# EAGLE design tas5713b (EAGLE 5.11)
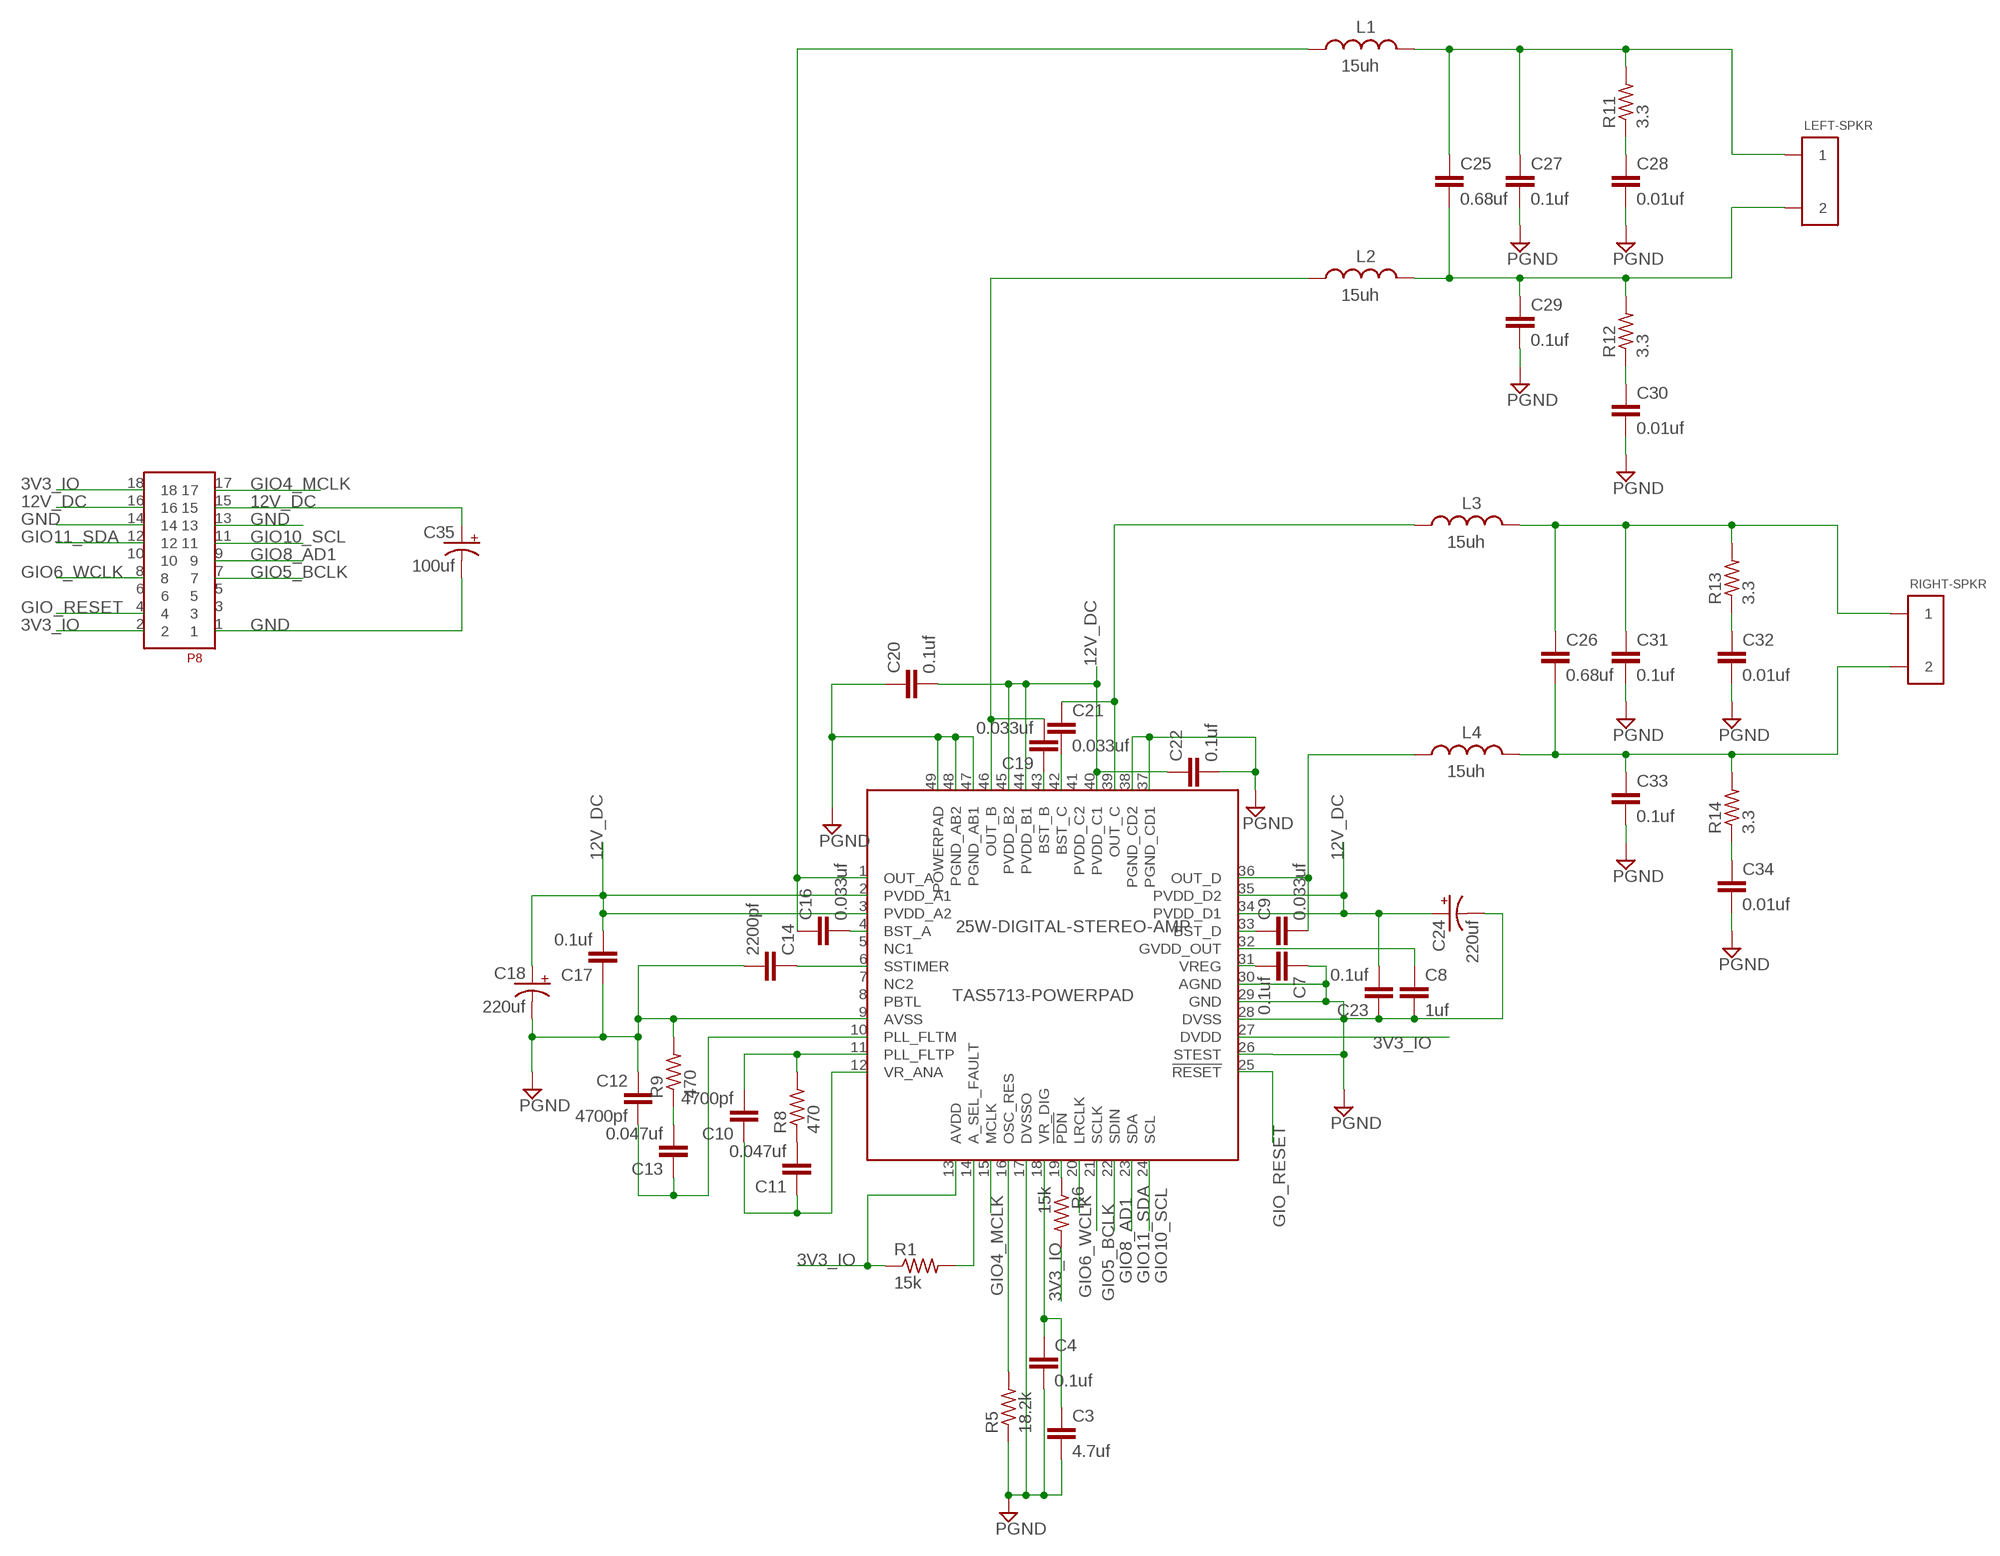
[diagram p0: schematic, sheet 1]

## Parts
25W-DIGITAL-STEREO-AMP  TAS5713-POWERPAD  [SCHMARTBOARD-VQFN48-POWERPAD]
C3  4.7uf  C-EUC1206  [C1206]
C4  0.1uf  C-EUC1206  [C1206]
C7  0.1uf  C-EUC1206  [C1206]
C8  1uf  C-EUC1206  [C1206]
C9  0.033uf  C-EUC1206  [C1206]
C10  4700pf  C-EUC1206  [C1206]
C11  0.047uf  C-EUC1206  [C1206]
C12  4700pf  C-EUC1206  [C1206]
C13  0.047uf  C-EUC1206  [C1206]
C14  2200pf  C-EUC1206  [C1206]
C16  0.033uf  C-EUC1206  [C1206]
C17  0.1uf  C-EUC1206  [C1206]
C18  220uf  CPOL-US175TMP-0808  [175TMP-0808]
C19  0.033uf  C-EUC1206  [C1206]
C20  0.1uf  C-EUC1206  [C1206]
C21  0.033uf  C-EUC1206  [C1206]
C22  0.1uf  C-EUC1206  [C1206]
C23  0.1uf  C-EUC1206  [C1206]
C24  220uf  CPOL-US175TMP-0808  [175TMP-0808]
C25  0.68uf  C-EUC1206  [C1206]
C26  0.68uf  C-EUC1206  [C1206]
C27  0.1uf  C-EUC1206  [C1206]
C28  0.01uf  C-EUC1206  [C1206]
C29  0.1uf  C-EUC1206  [C1206]
C30  0.01uf  C-EUC1206  [C1206]
C31  0.1uf  C-EUC1206  [C1206]
C32  0.01uf  C-EUC1206  [C1206]
C33  0.1uf  C-EUC1206  [C1206]
C34  0.01uf  C-EUC1206  [C1206]
C35  100uf  CPOL-US175TMP-0808  [175TMP-0808]
L1  15uh  INDUCTOR-ABRACON-1306S  [INDUCTOR-ABRACON-1306S]
L2  15uh  INDUCTOR-ABRACON-1306S  [INDUCTOR-ABRACON-1306S]
L3  15uh  INDUCTOR-ABRACON-1306S  [INDUCTOR-ABRACON-1306S]
L4  15uh  INDUCTOR-ABRACON-1306S  [INDUCTOR-ABRACON-1306S]
LEFT-SPKR  SCREW-CLAMP-2909  [SCREW-CLAMP-909]
P8  HEADER-2X9  [HEADER-2X9]
R1  15k  R-US_R1206  [R1206]
R5  18.2k  R-US_R1206  [R1206]
R6  15k  R-US_R1206  [R1206]
R8  470  R-US_R1206  [R1206]
R9  470  R-US_R1206  [R1206]
R11  3.3  R-US_R1206  [R1206]
R12  3.3  R-US_R1206  [R1206]
R13  3.3  R-US_R1206  [R1206]
R14  3.3  R-US_R1206  [R1206]
RIGHT-SPKR  SCREW-CLAMP-2909  [SCREW-CLAMP-909]

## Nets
3V3_IO: 25W-DIGITAL-STEREO-AMP.13(AVDD) 25W-DIGITAL-STEREO-AMP.27(DVDD) P8.2 P8.18 R1.1 R6.2
12V_DC: 25W-DIGITAL-STEREO-AMP.2(PVDD_A1) 25W-DIGITAL-STEREO-AMP.3(PVDD_A2) 25W-DIGITAL-STEREO-AMP.34(PVDD_D1) 25W-DIGITAL-STEREO-AMP.35(PVDD_D2) 25W-DIGITAL-STEREO-AMP.40(PVDD_C1) 25W-DIGITAL-STEREO-AMP.44(PVDD_B1) 25W-DIGITAL-STEREO-AMP.45(PVDD_B2) C17.2 C18.+ C20.2 C22.1 C23.2 C24.+ C35.+ P8.15 P8.16
GIO4_MCLK: 25W-DIGITAL-STEREO-AMP.15(MCLK) P8.17
GIO5_BCLK: 25W-DIGITAL-STEREO-AMP.21(SCLK) P8.7
GIO6_WCLK: 25W-DIGITAL-STEREO-AMP.20(LRCLK) P8.8
GIO8_AD1: 25W-DIGITAL-STEREO-AMP.22(SDIN) P8.9
GIO10_SCL: 25W-DIGITAL-STEREO-AMP.24(SCL) P8.11
GIO11_SDA: 25W-DIGITAL-STEREO-AMP.23(SDA) P8.12
GIO_RESET: 25W-DIGITAL-STEREO-AMP.25(!RESET) P8.4
GND: 25W-DIGITAL-STEREO-AMP.9(AVSS) 25W-DIGITAL-STEREO-AMP.17(DVSSO) 25W-DIGITAL-STEREO-AMP.26(STEST) 25W-DIGITAL-STEREO-AMP.28(DVSS) 25W-DIGITAL-STEREO-AMP.29(GND) 25W-DIGITAL-STEREO-AMP.30(AGND) 25W-DIGITAL-STEREO-AMP.37(PGND_CD1) 25W-DIGITAL-STEREO-AMP.38(PGND_CD2) 25W-DIGITAL-STEREO-AMP.47(PGND_AB1) 25W-DIGITAL-STEREO-AMP.48(PGND_AB2) 25W-DIGITAL-STEREO-AMP.49(POWERPAD) C3.2 C4.2 C7.1 C8.2 C12.1 C14.2 C17.1 C18.- C20.1 C22.2 C23.1 C24.- C27.2 C28.2 C29.2 C30.2 C31.2 C32.2 C33.2 C34.2 C35.- P8.1 P8.13 P8.14 R5.1 R9.2 ; supply symbol labelled PGND
N$1: 25W-DIGITAL-STEREO-AMP.4(BST_A) C16.2
N$2: 25W-DIGITAL-STEREO-AMP.1(OUT_A) C16.1 L1.1
N$3: 25W-DIGITAL-STEREO-AMP.43(BST_B) C19.1
N$4: 25W-DIGITAL-STEREO-AMP.46(OUT_B) C19.2 L2.1
N$5: 25W-DIGITAL-STEREO-AMP.42(BST_C) C21.2
N$6: 25W-DIGITAL-STEREO-AMP.14(A_SEL_FAULT) R1.2
N$7: 25W-DIGITAL-STEREO-AMP.33(BST_D) C9.1
N$8: 25W-DIGITAL-STEREO-AMP.36(OUT_D) C9.2 L4.1
N$9: 25W-DIGITAL-STEREO-AMP.31(VREG) C7.2
N$10: 25W-DIGITAL-STEREO-AMP.32(GVDD_OUT) C8.1
N$11: 25W-DIGITAL-STEREO-AMP.6(SSTIMER) C14.1
N$12: C28.1 R11.1
N$13: C25.2 C29.1 L2.2 LEFT-SPKR.2 R12.2
N$14: C30.1 R12.1
N$15: 25W-DIGITAL-STEREO-AMP.39(OUT_C) C21.1 L3.1
N$16: 25W-DIGITAL-STEREO-AMP.18(VR_DIG) C3.1 C4.1
N$17: 25W-DIGITAL-STEREO-AMP.16(OSC_RES) R5.2
N$18: C26.1 C31.1 L3.2 R13.2 RIGHT-SPKR.1
N$19: C25.1 C27.1 L1.2 LEFT-SPKR.1 R11.2
N$20: C32.1 R13.1
N$21: C26.2 C33.1 L4.2 R14.2 RIGHT-SPKR.2
N$22: C34.1 R14.1
N$23: 25W-DIGITAL-STEREO-AMP.19(!PDN) R6.1
N$24: 25W-DIGITAL-STEREO-AMP.10(PLL_FLTM) C12.2 C13.1
N$25: 25W-DIGITAL-STEREO-AMP.11(PLL_FLTP) C10.2 R8.2
N$26: 25W-DIGITAL-STEREO-AMP.12(VR_ANA) C10.1 C11.1
N$27: C11.2 R8.1
N$28: C13.2 R9.1
Unconnected: 25W-DIGITAL-STEREO-AMP.5(NC1) 25W-DIGITAL-STEREO-AMP.7(NC2) 25W-DIGITAL-STEREO-AMP.8(PBTL) 25W-DIGITAL-STEREO-AMP.41(PVDD_C2) P8.3 P8.5 P8.6 P8.10

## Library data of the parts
25W-DIGITAL-STEREO-AMP = trl:TAS5713-POWERPAD
C3 C4 C7-C14 C16 C17 C19-C23 C25-C34 = rcl:C-EU: CAPACITOR, European symbol
C18 C24 C35 = resistor:CPOL-US: POLARIZED CAPACITOR, American symbol
L1-L4 = trl:INDUCTOR-ABRACON-1306S
LEFT-SPKR RIGHT-SPKR = trl:SCREW-CLAMP-2
P8 = trl:HEADER-2X9
R1 R5 R6 R8 R9 R11-R14 = resistor:R-US_: RESISTOR, American symbol

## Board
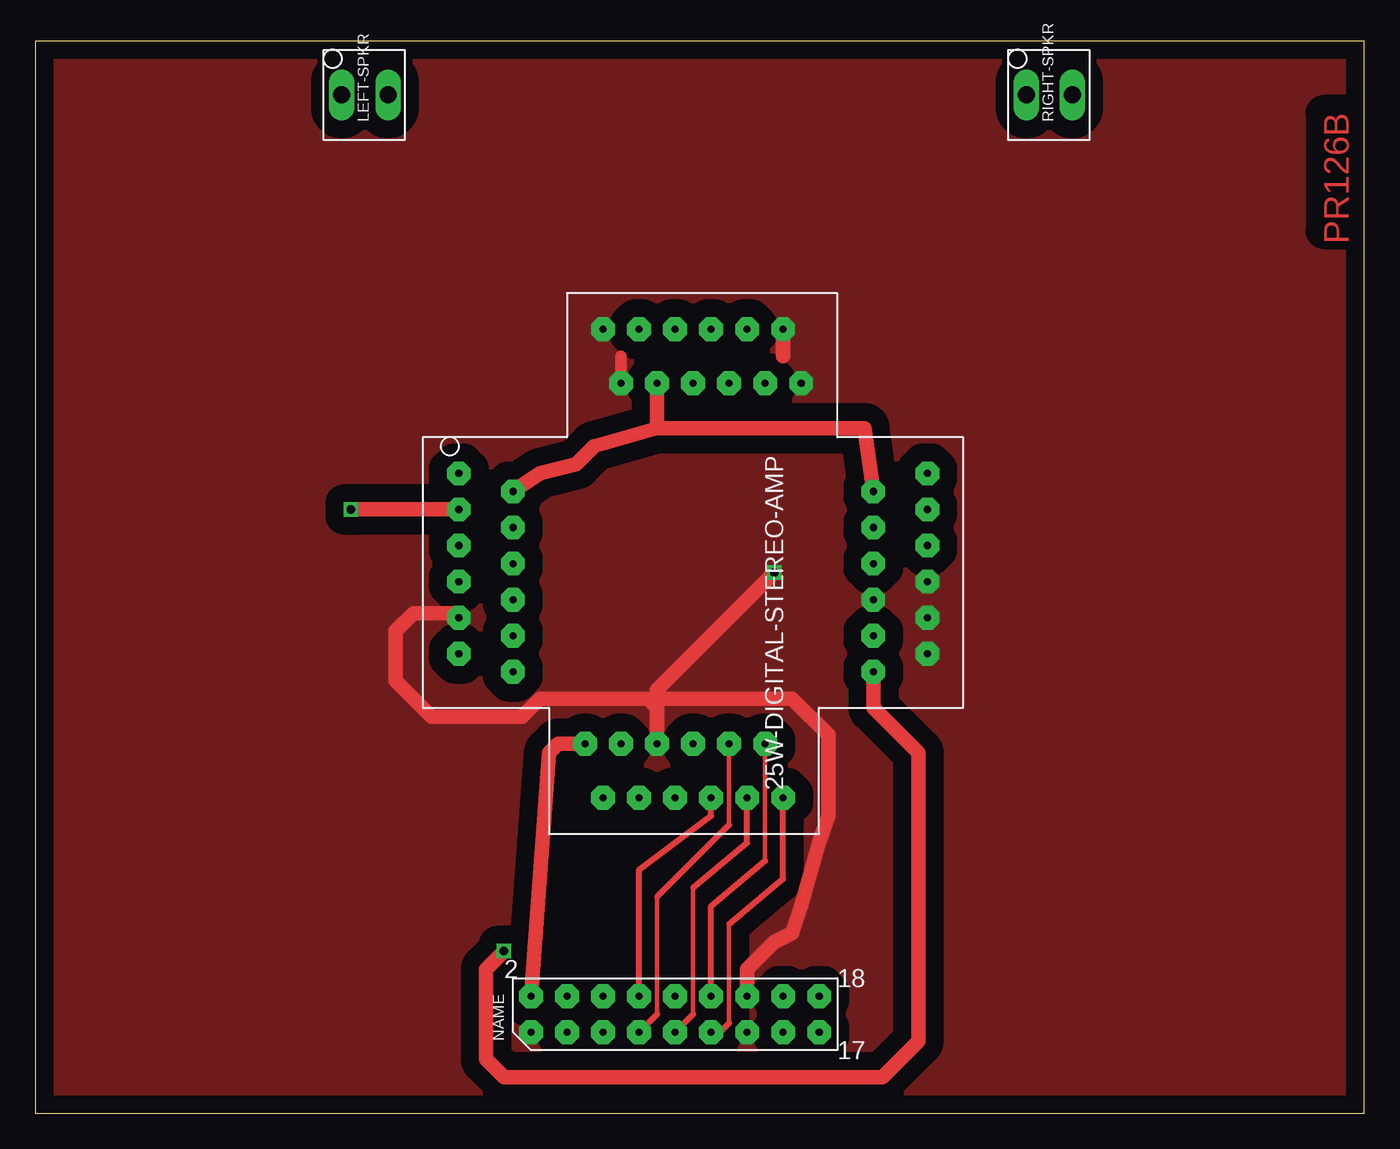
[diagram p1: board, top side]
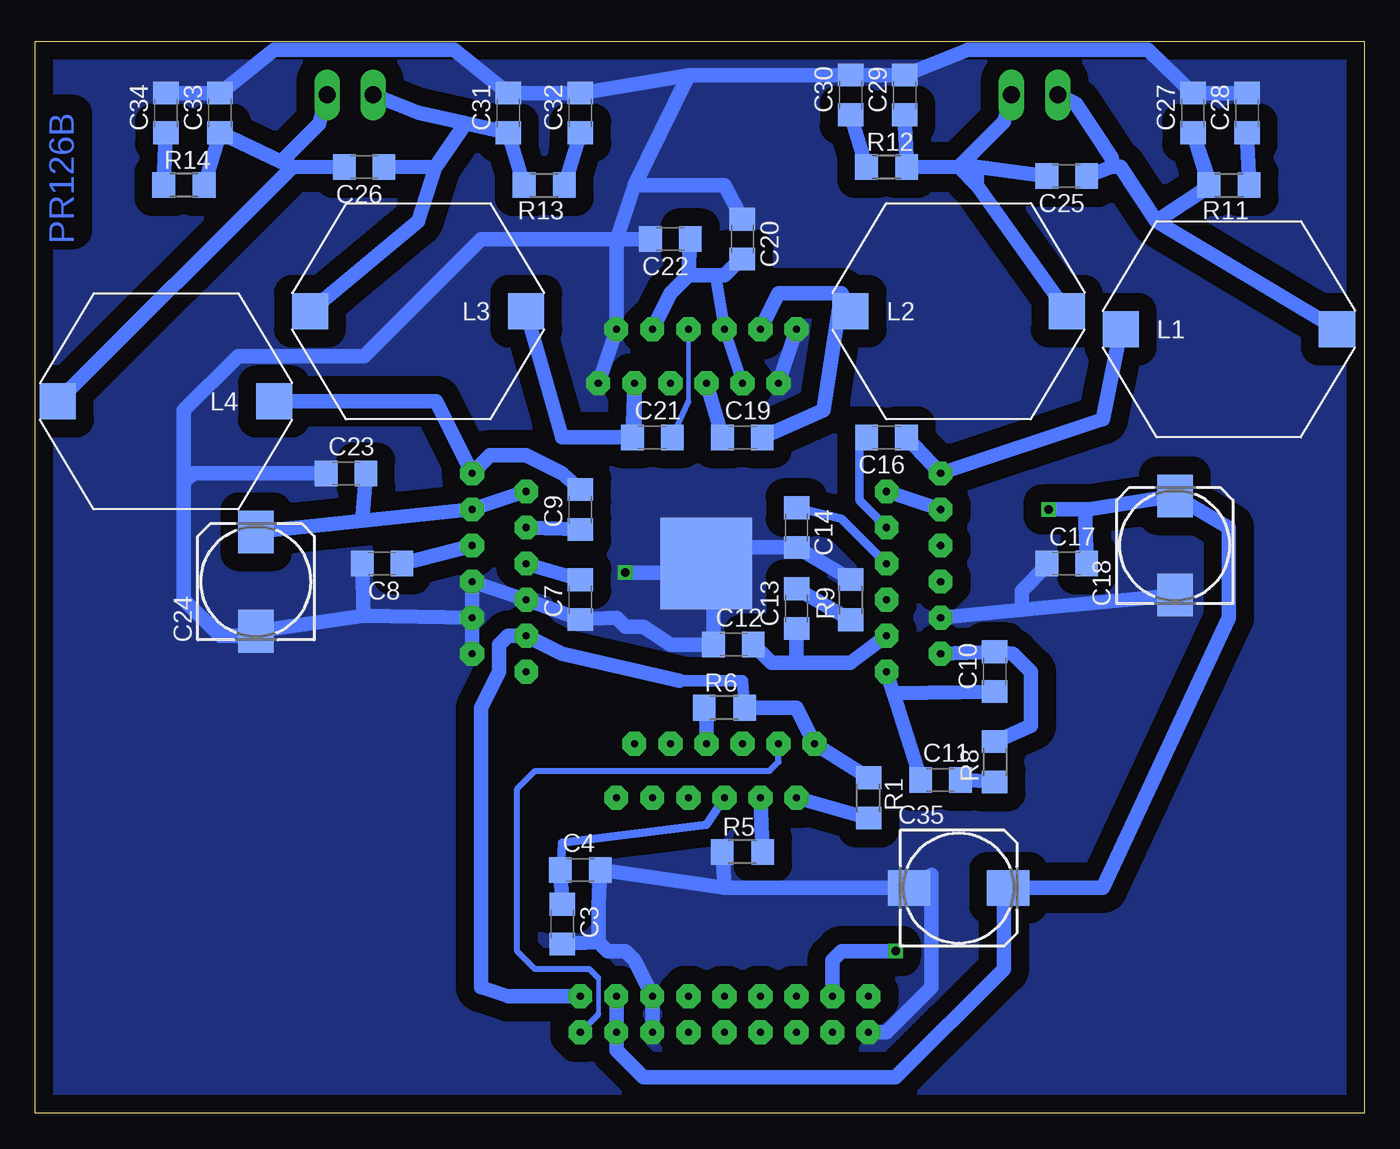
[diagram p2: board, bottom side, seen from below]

Size 93.65 x 75.56 mm. Coordinates in mm from the lower left corner, seen from the top.
Outline: 0,0 93.65,0 93.65,75.56 0,75.56 0,0
Copper layers (1*16): Top 0.035mm / dielectric 1.5mm / Bottom 0.035mm
Design rules "default": minimum track width 10mil, minimum drill 24mil, track to track 8mil, track to pad 8mil, pad to pad 8mil, via to via 8mil, smd to smd 8mil, copper to edge 40mil, drill to drill 8mil, minimum pad ring 10mil, minimum via ring 8mil, stop-mask expansion 4mil, vias tented up to drill 0mil, thermal gap 10mil

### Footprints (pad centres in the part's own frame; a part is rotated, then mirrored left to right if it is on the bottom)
SCHMARTBOARD-VQFN48-POWERPAD = drill 0.5 pad 1.676 octagon: 1 -6.35,-16.51; 2 -5.08,-12.7; 3 -3.81,-16.51; 4 -2.54,-12.7; 5 -1.27,-16.51; 6 0,-12.7; 7 1.27,-16.51; 8 2.54,-12.7; 9 3.81,-16.51; 10 5.08,-12.7; 11 6.35,-16.51; 12 7.62,-12.7; 13 12.7,-7.62; 14 16.51,-6.35; 15 12.7,-5.08; 16 16.51,-3.81; 17 12.7,-2.54; 18 16.51,-1.27; 19 12.7,0; 20 16.51,1.27; 21 12.7,2.54; 22 16.51,3.81; 23 12.7,5.08; 24 16.51,6.35; 25 7.62,12.7; 26 6.35,16.51; 27 5.08,12.7; 28 3.81,16.51; 29 2.54,12.7; 30 1.27,16.51; 31 0,12.7; 32 -1.27,16.51; 33 -2.54,12.7; 34 -3.81,16.51; 35 -5.08,12.7; 36 -6.35,16.51; 37 -12.7,7.62; 38 -16.51,6.35; 39 -12.7,5.08; 40 -16.51,3.81; 41 -12.7,2.54; 42 -16.51,1.27; 43 -12.7,0; 44 -16.51,-1.27; 45 -12.7,-2.54; 46 -16.51,-3.81; 47 -12.7,-5.08; 48 -16.51,-6.35 | smd 6.452 x 6.452 bottom: 49 0,0
C1206 = smd 1.6 x 1.8: 1 -1.4,0; 2 1.4,0
175TMP-0808 = smd 3 x 2.5: + 3.5,0; - -3.5,0
INDUCTOR-ABRACON-1306S = smd 2.54 x 2.54: 1 0,0; 2 15.24,0
SCREW-CLAMP-909 = drill 1.2 long: 1 0,0; 2 3.251,0
HEADER-2X9 = drill 0.5 pad 1.676 octagon: 1 -11.43,-1.27; 2 -11.43,1.27; 3 -8.89,-1.27; 4 -8.89,1.27; 5 -6.35,-1.27; 6 -6.35,1.27; 7 -3.81,-1.27; 8 -3.81,1.27; 9 -1.27,-1.27; 10 -1.27,1.27; 11 1.27,-1.27; 12 1.27,1.27; 13 3.81,-1.27; 14 3.81,1.27; 15 6.35,-1.27; 16 6.35,1.27; 17 8.89,-1.27; 18 8.89,1.27
R1206 = smd 1.6 x 1.803: 1 -1.422,0; 2 1.422,0

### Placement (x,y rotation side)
25W-DIGITAL-STEREO-AMP  46.35,38.73 270 top
C3  56.52,13.34 270 bottom
C4  55.24,17.14 0 bottom
C7  55.24,36.2 90 bottom
C8  69.22,38.73 180 bottom
C9  55.24,42.55 90 bottom
C10  26.04,31.11 90 bottom
C11  29.84,23.5 0 bottom
C12  44.45,33.02 0 bottom
C13  40.01,35.56 90 bottom
C14  40.01,41.27 270 bottom
C16  33.66,47.62 180 bottom
C17  20.95,38.73 0 bottom
C18  13.34,40.01 90 bottom
C19  43.81,47.62 0 bottom
C20  43.81,61.59 270 bottom
C21  50.16,47.62 0 bottom
C22  48.9,61.59 180 bottom
C23  71.75,45.09 0 bottom
C24  78.11,37.47 90 bottom
C25  20.95,66.04 180 bottom
C26  70.48,66.67 180 bottom
C27  12.06,70.48 90 bottom
C28  8.26,70.48 90 bottom
C29  32.38,71.75 90 bottom
C30  36.2,71.75 90 bottom
C31  60.33,70.48 90 bottom
C32  55.24,70.48 90 bottom
C33  80.64,70.48 90 bottom
C34  84.45,70.48 90 bottom
C35  28.57,15.88 0 bottom
L1  17.14,55.24 0 bottom
L2  36.2,56.52 0 bottom
L3  59.05,56.52 180 bottom
L4  76.83,50.16 180 bottom
LEFT-SPKR  21.59,71.75 0 top
P8  46.35,6.99 0 top
R1  34.92,22.23 270 bottom
R5  43.81,18.41 0 bottom
R6  45.09,28.57 0 bottom
R8  26.04,24.77 90 bottom
R9  36.2,36.2 90 bottom
R11  9.53,65.41 180 bottom
R12  33.66,66.67 0 bottom
R13  57.78,65.41 180 bottom
R14  83.19,65.41 0 bottom
RIGHT-SPKR  69.85,71.75 0 top

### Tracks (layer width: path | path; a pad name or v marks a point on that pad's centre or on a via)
3V3_IO
  Top 1.016: P8.2 36.2,25.4 36.83,26.04 25W-DIGITAL-STEREO-AMP.13
  Bottom 0.813: R6.2 43.81,30.48 48.26,30.48
  Bottom 1.016: 48.26,30.48 56.52,32.38 25W-DIGITAL-STEREO-AMP.27 60.33,33.66 60.96,33.02 60.96,31.11 62.23,28.57 62.23,8.89 60.33,8.26 P8.18 | R1.1 25W-DIGITAL-STEREO-AMP.13 40.01,28.57 R6.2
12V_DC  (via drill 0.6)
  Top 1.016: 43.81,48.26 58.42,48.26 25W-DIGITAL-STEREO-AMP.35 | 25W-DIGITAL-STEREO-AMP.2 35.56,45.09 38.1,45.72 39.37,46.99 43.81,48.26 | v22.23,42.55 25W-DIGITAL-STEREO-AMP.3 | 43.81,48.26 25W-DIGITAL-STEREO-AMP.45
  Bottom 0.813: 25W-DIGITAL-STEREO-AMP.45 25W-DIGITAL-STEREO-AMP.44 45.72,59.05
  Bottom 1.016: 72.92,41.5 25W-DIGITAL-STEREO-AMP.34 25W-DIGITAL-STEREO-AMP.35 | 72.92,41.5 C24.+ | 25W-DIGITAL-STEREO-AMP.3 25W-DIGITAL-STEREO-AMP.2 | 47.62,59.05 48.9,57.78 25W-DIGITAL-STEREO-AMP.40 | 47.62,59.05 45.72,59.05 45.09,59.05 43.95,60.2 C20.2 | 19.68,42.55 19.38,42.55 C18.+ 9.53,41.27 9.53,34.92 18.41,15.88 C35.+ 25.4,15.55 25.4,10.16 33.02,2.54 50.8,2.54 52.7,4.45 P8.15 P8.16 | 19.68,42.55 v22.23,42.55 | C23.2 70.61,41.74 72.92,41.5 | 19.68,42.55 C17.2 | 47.62,59.05 C22.1
GIO4_MCLK
  Bottom 0.305: 53.98,6.99 53.98,9.53
  Bottom 0.406: 25W-DIGITAL-STEREO-AMP.15 41.27,24.77 41.91,24.13 58.42,24.13 59.69,22.86 59.69,11.43 58.42,10.16 54.61,10.16 53.98,9.53 | P8.17 53.98,6.99
GIO5_BCLK
  Top 0.305: 43.81,6.99 43.81,15.24 | 48.9,20.32 25W-DIGITAL-STEREO-AMP.21
  Top 0.406: P8.7 43.81,6.99 | 43.81,15.24 48.9,20.32
GIO6_WCLK
  Top 0.406: P8.8 42.55,17.14 47.62,20.95 25W-DIGITAL-STEREO-AMP.20
GIO8_AD1
  Top 0.305: 46.35,6.99 46.35,15.88
  Top 0.406: P8.9 46.35,6.99 | 46.35,15.88 50.16,19.05 25W-DIGITAL-STEREO-AMP.22
GIO10_SCL
  Top 0.305: 48.9,6.35 48.9,13.34
  Top 0.406: P8.11 48.26,5.71 48.9,6.35 | 48.9,13.34 52.7,16.51 25W-DIGITAL-STEREO-AMP.24
GIO11_SDA
  Top 0.305: 51.44,17.78 25W-DIGITAL-STEREO-AMP.23
  Top 0.406: P8.12 47.62,14.61 51.44,17.78
GIO_RESET  (via drill 0.6)
  Top 1.016: 25W-DIGITAL-STEREO-AMP.25 59.05,28.57 62.23,25.4 62.23,5.08 59.69,2.54 33.02,2.54 31.75,3.81 31.75,10.16 v33.02,11.43
  Bottom 1.016: v33.02,11.43 36.83,11.43 37.47,10.79 P8.4
GND  (via drill 0.6)
  Top 0.813: 25W-DIGITAL-STEREO-AMP.47 41.27,53.34
  Top 1.016: v52.07,38.1 43.81,29.84 25W-DIGITAL-STEREO-AMP.17 43.81,28.57 43.18,29.21 | 25W-DIGITAL-STEREO-AMP.38 52.7,53.34 | 43.18,29.21 35.56,29.21 34.29,27.94 27.94,27.94 25.4,30.48 25.4,33.99 26.64,35.23 29.54,35.23 25W-DIGITAL-STEREO-AMP.9 | 43.18,29.21 53.34,29.21 55.88,26.67 55.88,20.95 55.24,19.05 53.98,14.61 53.34,12.7 52.07,12.06 50.16,10.16 P8.14
  Bottom 1.016: C28.2 C27.2 15.24,74.93 27.94,74.93 C29.2 C30.2 47.62,73.16 | C34.2 C33.2 76.83,74.93 64.14,74.93 C31.2 C32.2 47.62,73.16 | 52.7,61.59 51.44,65.41 | 51.44,65.41 47.62,73.16 | 25W-DIGITAL-STEREO-AMP.37 25W-DIGITAL-STEREO-AMP.38 52.7,61.59 | 25W-DIGITAL-STEREO-AMP.48 25W-DIGITAL-STEREO-AMP.47 | 25W-DIGITAL-STEREO-AMP.28 70.52,35.06 | 70.52,35.06 C24.- 78.42,33.66 80.64,33.66 83.19,36.2 83.19,44.45 | 70.52,35.06 C8.2 | 25W-DIGITAL-STEREO-AMP.28 25W-DIGITAL-STEREO-AMP.30 25W-DIGITAL-STEREO-AMP.29 C7.1 52.7,34.92 52.07,34.29 50.8,34.29 48.9,33.02 C12.1 45.85,38.23 25W-DIGITAL-STEREO-AMP.49 | 25W-DIGITAL-STEREO-AMP.28 25W-DIGITAL-STEREO-AMP.26 | 53.98,12.06 C3.2 | 53.98,12.06 53.98,14.61 C4.2 45.09,15.88 | R9.2 C14.2 45.22,39.88 25W-DIGITAL-STEREO-AMP.49 | 24.12,35.47 C18.- | 25W-DIGITAL-STEREO-AMP.9 24.12,35.47 | 45.09,15.88 C35.- 30.48,16.82 30.48,8.89 33.66,5.71 P8.1 | 45.09,15.88 R5.1 | 52.7,61.59 C22.2 | 51.44,65.41 45.09,65.41 C20.1 | P8.13 P8.14 51.44,10.79 52.07,11.43 53.34,11.43 53.98,12.06 | v52.07,38.1 46.99,38.1 25W-DIGITAL-STEREO-AMP.49 | C17.1 22.36,38.6 24.13,36.83 24.13,35.48 24.12,35.47 | 52.7,61.59 62.23,61.59 70.48,53.34 79.38,53.34 83.19,49.53 83.19,44.45 | C23.1 82.55,45.09 83.19,44.45
  pour Top (isolate 1.27, no thermals): 0,76.2 93.98,76.2 93.98,0 0,0
  pour Bottom (isolate 1.27, no thermals): 0,76.2 93.98,76.2 93.98,0 0,0
N$1
  Bottom 0.61: 25W-DIGITAL-STEREO-AMP.4 34.92,42.55 35.56,43.18 35.56,47.62 C16.2
N$2
  Bottom 1.016: L1.1 18.41,48.9 25W-DIGITAL-STEREO-AMP.1 C16.1
N$3
  Bottom 1.016: C19.1 25W-DIGITAL-STEREO-AMP.43
N$4
  Bottom 1.016: 36.83,57.78 L2.1 | 36.83,57.78 41.27,57.78 25W-DIGITAL-STEREO-AMP.46 | C19.2 38.1,49.53 36.83,57.78
N$5
  Bottom 0.305: 47.62,50.16 25W-DIGITAL-STEREO-AMP.42
  Bottom 0.406: C21.2 47.62,50.16
N$6
  Bottom 1.016: R1.2 25W-DIGITAL-STEREO-AMP.14
N$7
  Bottom 1.016: C9.1 25W-DIGITAL-STEREO-AMP.33
N$8
  Bottom 1.016: L4.1 65.41,50.16 25W-DIGITAL-STEREO-AMP.36 61.59,46.35 59.05,46.35 56.52,45.09 C9.2
N$9
  Bottom 1.016: C7.2 25W-DIGITAL-STEREO-AMP.31
N$10
  Bottom 1.016: 25W-DIGITAL-STEREO-AMP.32 C8.1
N$11
  Bottom 0.61: 25W-DIGITAL-STEREO-AMP.6 35.56,40.64 36.83,41.91 C14.1
N$12
  Bottom 1.016: R11.1 C28.1
N$13
  Bottom 1.016: 27.29,65.41 27.28,66.69 C25.2 | L2.2 27.29,65.41 | C29.1 R12.2 28.56,66.71 | 27.29,65.41 28.56,66.71 | LEFT-SPKR.2 25.4,69.87 28.56,66.71
N$14
  Bottom 1.016: R12.1 C30.1
N$15
  Bottom 1.016: C21.1 25W-DIGITAL-STEREO-AMP.39 51.44,47.62 56.52,47.62 L3.1
N$16
  Bottom 0.61: C4.1 56.52,19.05 46.35,20.32 25W-DIGITAL-STEREO-AMP.18
  Bottom 1.016: C4.1 C3.1
N$17
  Bottom 1.016: R5.2 25W-DIGITAL-STEREO-AMP.16
N$18
  Bottom 1.016: L3.2 66.67,62.87 65.44,66.69 | 65.44,66.69 C26.1 | R13.2 C31.1 63.34,69.74 | 63.34,69.74 65.44,66.69 | RIGHT-SPKR.1 66.63,70.48 63.34,69.74
N$19
  Bottom 1.016: R11.2 C27.1 10.79,65.41 14.62,62.87 | L1.2 14.62,62.87 | 14.62,62.87 17.17,66.69 17.78,66.68 | 17.78,66.68 C25.1 | LEFT-SPKR.1 20.32,71.12 17.78,67.31 17.78,66.69 17.78,66.68
N$20
  Bottom 1.016: R13.1 C32.1
N$21
  Bottom 1.016: 75.54,66.69 L4.2 | C26.2 75.54,66.69 | 75.54,66.69 76.32,67.05 | 76.32,67.05 C33.1 R14.2 | RIGHT-SPKR.2 73.66,69.71 76.32,67.05
N$22
  Bottom 1.016: R14.1 C34.1
N$23
  Bottom 1.016: 25W-DIGITAL-STEREO-AMP.19 46.35,28.57 R6.1
N$24
  Bottom 1.016: 25W-DIGITAL-STEREO-AMP.10 36.2,31.75 40.01,31.75 | 40.01,31.75 41.78,31.75 C12.2 | 40.01,31.75 C13.1
N$25
  Bottom 1.016: R8.2 23.5,27.3 23.5,31.11 24.77,32.38 C10.2 25W-DIGITAL-STEREO-AMP.11
N$26
  Bottom 1.016: C11.1 33.17,29.59 | 33.17,29.59 25W-DIGITAL-STEREO-AMP.12 | 33.17,29.59 C10.1
N$27
  Bottom 1.016: R8.1 C11.2
N$28
  Bottom 1.016: R9.1 C13.2

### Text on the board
Top: PR126B
Bottom: PR126B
